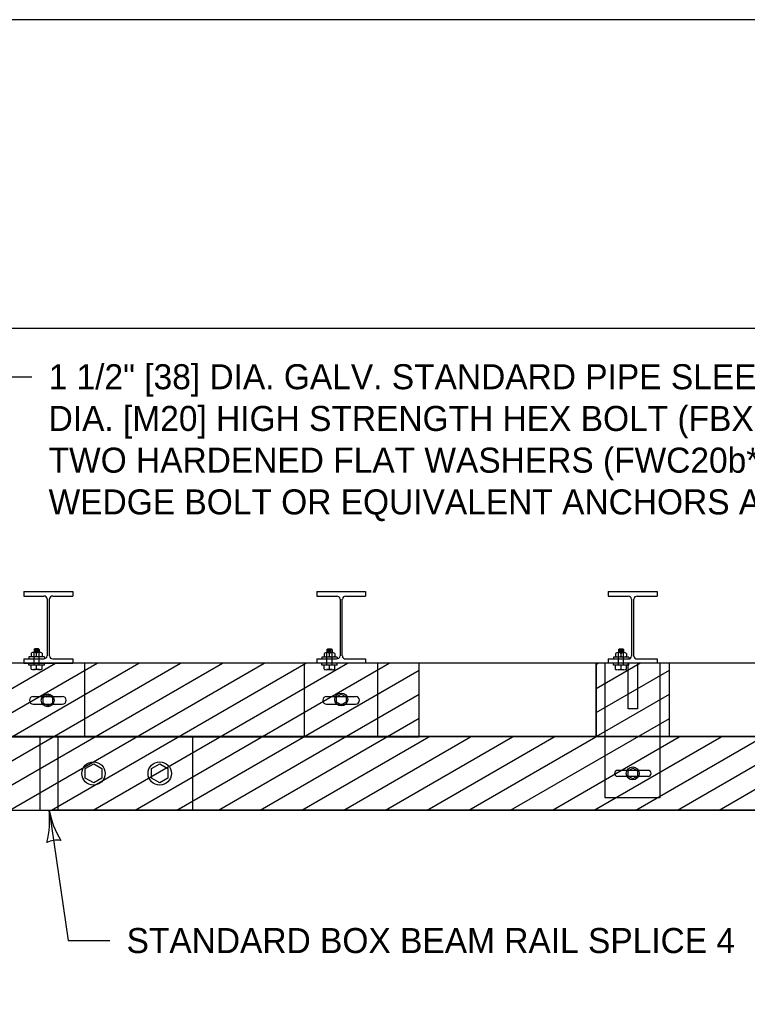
# Model space of a CAD drawing. Extents: x 49983 to 50021, y 49963.5 to 50011.4.
# Drawn here: x 50005.363 to 50007.107, y 49996.667 to 49998.999 of the extents above; entities that cross this region are included whole.
import ezdxf

# ---------------------------------------------------------------- set-up
doc = ezdxf.new("R2010")
doc.units = 0
for name, color, linetype in [('Level 1', 7, 'Continuous'), ('Level 10', 7, 'Continuous'), ('Level 2', 7, 'Continuous'), ('Level 3', 7, 'Continuous'), ('Level 4', 7, 'Continuous')]:
    doc.layers.add(name, color=color, linetype=linetype)

msp = doc.modelspace()

# ---------------------------------------------------------------- linework, layer by layer
at = {"layer": 'Level 1'}
for p, q in [((50005.3733, 49997.628), (50005.4904, 49997.628)), ((50005.3733, 49997.628), (50005.3733, 49997.617)), ((50005.4904, 49997.628), (50005.4904, 49997.617)), ((50006.0751, 49997.6278), (50006.1922, 49997.6278)), ((50006.0751, 49997.6278), (50006.0751, 49997.6168)), ((50006.1922, 49997.6278), (50006.1922, 49997.6168)), ((50006.7737, 49997.6277), (50006.8908, 49997.6277)), ((50006.7737, 49997.6277), (50006.7737, 49997.6167)), ((50006.8908, 49997.6277), (50006.8908, 49997.6167)), ((50005.3733, 49997.617), (50005.421, 49997.617)), ((50005.429, 49997.6102), (50005.429, 49997.4739)), ((50005.4346, 49997.4737), (50005.4346, 49997.6102)), ((50005.4427, 49997.617), (50005.4904, 49997.617)), ((50006.0751, 49997.6168), (50006.1229, 49997.6168)), ((50006.1309, 49997.61), (50006.1309, 49997.4737)), ((50006.1364, 49997.4736), (50006.1364, 49997.61)), ((50006.1446, 49997.6168), (50006.1922, 49997.6168)), ((50006.7737, 49997.6167), (50006.8215, 49997.6167)), ((50006.8295, 49997.6098), (50006.8295, 49997.4735)), ((50006.835, 49997.4733), (50006.835, 49997.6098)), ((50006.8432, 49997.6167), (50006.8908, 49997.6167)), ((50005.3977, 49997.4892), (50005.3989, 49997.4904)), ((50005.3977, 49997.4892), (50005.4099, 49997.4892)), ((50005.3977, 49997.4892), (50005.3977, 49997.482)), ((50005.4087, 49997.4904), (50005.3989, 49997.4904)), ((50005.4081, 49997.4873), (50005.3996, 49997.4873)), ((50005.4081, 49997.4861), (50005.3996, 49997.4861)), ((50005.4081, 49997.4849), (50005.3996, 49997.4849)), ((50005.4099, 49997.4892), (50005.4087, 49997.4904)), ((50005.4099, 49997.4892), (50005.4099, 49997.482)), ((50006.0996, 49997.489), (50006.1008, 49997.4902)), ((50006.0996, 49997.489), (50006.1117, 49997.489)), ((50006.0996, 49997.489), (50006.0996, 49997.4817)), ((50006.1105, 49997.4902), (50006.1008, 49997.4902)), ((50006.11, 49997.4871), (50006.1014, 49997.4871)), ((50006.11, 49997.4859), (50006.1014, 49997.4859)), ((50006.11, 49997.4847), (50006.1014, 49997.4847)), ((50006.1117, 49997.489), (50006.1105, 49997.4902)), ((50006.1117, 49997.489), (50006.1117, 49997.4817)), ((50006.7982, 49997.4888), (50006.7994, 49997.49)), ((50006.7982, 49997.4888), (50006.8103, 49997.4888)), ((50006.7982, 49997.4888), (50006.7982, 49997.4816)), ((50006.8091, 49997.49), (50006.7994, 49997.49)), ((50006.8086, 49997.487), (50006.8, 49997.487)), ((50006.8086, 49997.4857), (50006.8, 49997.4857)), ((50006.8086, 49997.4845), (50006.8, 49997.4845)), ((50006.8103, 49997.4888), (50006.8091, 49997.49)), ((50006.8103, 49997.4888), (50006.8103, 49997.4816)), ((50005.3733, 49997.467), (50005.3733, 49997.456)), ((50005.3733, 49997.467), (50005.421, 49997.467)), ((50005.4225, 49997.4713), (50005.3853, 49997.4713)), ((50005.3853, 49997.4713), (50005.3853, 49997.467)), ((50005.3907, 49997.4799), (50005.3907, 49997.4734)), ((50005.4104, 49997.482), (50005.3972, 49997.482)), ((50005.4081, 49997.4837), (50005.3996, 49997.4837)), ((50005.4038, 49997.4734), (50005.4038, 49997.4799)), ((50005.4169, 49997.4799), (50005.4169, 49997.4734)), ((50005.4225, 49997.4713), (50005.4225, 49997.467)), ((50005.4425, 49997.467), (50005.4904, 49997.467)), ((50005.4904, 49997.467), (50005.4904, 49997.456)), ((50005.4904, 49997.467), (50005.4904, 49997.456)), ((50006.0751, 49997.4667), (50006.0751, 49997.4558)), ((50006.0751, 49997.4667), (50006.1228, 49997.4667)), ((50006.1244, 49997.4711), (50006.0872, 49997.4711)), ((50006.0872, 49997.4711), (50006.0872, 49997.4667)), ((50006.0925, 49997.4797), (50006.0925, 49997.4731)), ((50006.1122, 49997.4817), (50006.0991, 49997.4817)), ((50006.11, 49997.4834), (50006.1014, 49997.4834)), ((50006.1057, 49997.4731), (50006.1057, 49997.4797)), ((50006.1188, 49997.4797), (50006.1188, 49997.4731)), ((50006.1244, 49997.4711), (50006.1244, 49997.4668)), ((50006.1444, 49997.4667), (50006.1922, 49997.4667)), ((50006.1922, 49997.4667), (50006.1922, 49997.4558)), ((50006.1922, 49997.4667), (50006.1922, 49997.4558)), ((50006.7737, 49997.4666), (50006.8214, 49997.4666)), ((50006.7737, 49997.4666), (50006.7737, 49997.456)), ((50006.823, 49997.471), (50006.7858, 49997.471)), ((50006.7858, 49997.471), (50006.7858, 49997.4666)), ((50006.7911, 49997.4796), (50006.7911, 49997.473)), ((50006.8108, 49997.4816), (50006.7977, 49997.4816)), ((50006.8086, 49997.4833), (50006.8, 49997.4833)), ((50006.8042, 49997.473), (50006.8042, 49997.4796)), ((50006.8174, 49997.4796), (50006.8174, 49997.473)), ((50006.823, 49997.471), (50006.823, 49997.4666)), ((50006.843, 49997.4666), (50006.8908, 49997.4666)), ((50006.8908, 49997.4666), (50006.8908, 49997.456)), ((50006.3204, 49997.456), (50003.275, 49997.456)), ((50004.8396, 49997.1042), (50005.4489, 49997.456)), ((50004.9396, 49997.1042), (50005.5489, 49997.456)), ((50005.0396, 49997.1042), (50005.6489, 49997.456)), ((50009.122, 49997.456), (50005.1235, 49997.456)), ((50005.1396, 49997.1042), (50005.7489, 49997.456)), ((50005.2396, 49997.1042), (50005.8489, 49997.456)), ((50005.3396, 49997.1042), (50005.9489, 49997.456)), ((50005.4977, 49997.456), (50005.3659, 49997.456)), ((50005.3733, 49997.456), (50005.4904, 49997.456)), ((50005.4396, 49997.1042), (50006.0489, 49997.456)), ((50005.5396, 49997.1042), (50006.1489, 49997.456)), ((50005.6396, 49997.1042), (50006.2489, 49997.456)), ((50005.7396, 49997.1042), (50006.3204, 49997.4396)), ((50006.3204, 49997.2803), (50006.3204, 49997.456)), ((50006.7444, 49997.2799), (50006.7444, 49997.456)), ((50006.7444, 49997.4534), (50006.7489, 49997.456)), ((50006.7444, 49997.3957), (50006.8489, 49997.456)), ((50006.7444, 49997.338), (50006.9201, 49997.4394)), ((50006.9201, 49997.2799), (50006.9201, 49997.456)), ((50005.4192, 49997.3737), (50005.4305, 49997.3802)), ((50005.4192, 49997.3605), (50005.4192, 49997.3737)), ((50005.4305, 49997.3802), (50005.4417, 49997.3737)), ((50005.4417, 49997.3737), (50005.4417, 49997.3605)), ((50005.8396, 49997.1042), (50006.3204, 49997.3818)), ((50006.1227, 49997.3757), (50006.134, 49997.3822)), ((50006.1227, 49997.3626), (50006.1227, 49997.3757)), ((50006.134, 49997.3822), (50006.1452, 49997.3757)), ((50006.1452, 49997.3757), (50006.1452, 49997.3626)), ((50006.7444, 49997.2802), (50006.9201, 49997.3817)), ((50005.4305, 49997.3544), (50005.4192, 49997.3605)), ((50005.4417, 49997.3605), (50005.4305, 49997.3544)), ((50006.134, 49997.3565), (50006.1227, 49997.3626)), ((50006.1452, 49997.3626), (50006.134, 49997.3565)), ((50005.9396, 49997.1042), (50006.3204, 49997.3241)), ((50006.5396, 49997.1042), (50006.9201, 49997.3239)), ((50003.2457, 49997.2799), (50005.4468, 49997.2799)), ((50006.3204, 49997.2803), (50003.275, 49997.2803)), ((50009.1498, 49997.2803), (50005.1235, 49997.2803)), ((50005.4124, 49997.1041), (50005.4124, 49997.2798)), ((50005.455, 49997.2798), (50005.455, 49997.1041)), ((50006.0396, 49997.1042), (50006.3439, 49997.2799)), ((50006.1396, 49997.1042), (50006.4439, 49997.2799)), ((50006.2396, 49997.1042), (50006.5439, 49997.2799)), ((50013.5013, 49997.2799), (50006.3204, 49997.2799)), ((50006.3396, 49997.1042), (50006.6439, 49997.2799)), ((50006.4396, 49997.1042), (50006.7439, 49997.2799)), ((50006.6396, 49997.1042), (50006.9439, 49997.2799)), ((50006.7396, 49997.1042), (50007.0439, 49997.2799)), ((50006.7664, 49997.2799), (50006.7444, 49997.2799)), ((50006.8982, 49997.2799), (50006.7664, 49997.2799)), ((50006.8396, 49997.1042), (50007.1439, 49997.2799)), ((50006.9201, 49997.2799), (50006.8982, 49997.2799)), ((50006.9396, 49997.1042), (50007.2439, 49997.2799)), ((50007.0396, 49997.1042), (50007.3439, 49997.2799)), ((50005.5205, 49997.2037), (50005.5406, 49997.215)), ((50005.5406, 49997.215), (50005.5598, 49997.2037)), ((50005.6793, 49997.2037), (50005.6994, 49997.215)), ((50005.6994, 49997.215), (50005.7186, 49997.2037)), ((50006.8213, 49997.1985), (50006.8325, 49997.2049)), ((50006.8325, 49997.2049), (50006.8435, 49997.1985)), ((50005.5205, 49997.1803), (50005.5205, 49997.2037)), ((50005.5598, 49997.2037), (50005.5598, 49997.1803)), ((50005.6793, 49997.1803), (50005.6793, 49997.2037)), ((50005.7186, 49997.2037), (50005.7186, 49997.1803)), ((50006.8213, 49997.1857), (50006.8213, 49997.1985)), ((50006.8325, 49997.1793), (50006.8213, 49997.1857)), ((50006.8435, 49997.1857), (50006.8325, 49997.1793)), ((50006.8435, 49997.1985), (50006.8435, 49997.1857)), ((50005.5406, 49997.1691), (50005.5205, 49997.1803)), ((50005.5598, 49997.1803), (50005.5406, 49997.1691)), ((50005.6994, 49997.1691), (50005.6793, 49997.1803)), ((50005.7186, 49997.1803), (50005.6994, 49997.1691)), ((50003.2457, 49997.1042), (50005.4468, 49997.1042)), ((50013.5013, 49997.1042), (50005.4468, 49997.1042))]:
    msp.add_line(p, q, dxfattribs=at)
msp.add_lwpolyline([(49999.3835, 49998.9992), (50016.7501, 49998.9992), (50016.7501, 49987.7988), (49999.3835, 49987.7988)], close=True, dxfattribs=at)
for points in [[(50006.7444, 49997.2799), (50006.3204, 49997.2799), (50006.3204, 49997.456), (50003.275, 49997.456), (50003.275, 49997.2799), (50003.2457, 49997.2799), (50002.2562, 49997.4473), (50002.2558, 49997.4447), (50002.2559, 49997.452), (50001.5623, 49997.4576), (50001.5622, 49997.4503), (50001.7737, 49997.3496), (50002.2274, 49997.2739), (50003.2457, 49997.1042), (50005.4468, 49997.1042), (50005.4633, 49997.1042), (50015.1856, 49997.1042), (50015.1855, 49997.1666), (50015.1344, 49997.1847), (50015.2365, 49997.2209), (50015.1855, 49997.239), (50015.1855, 49997.2799), (50012.5423, 49997.2799)], [(50006.9201, 49997.2799), (50006.9201, 49997.456), (50006.7444, 49997.456), (50006.7444, 49997.2799)], [(50005.4468, 49997.2799), (50006.3204, 49997.2799), (50006.3204, 49997.2803)], [(50007.4472, 49997.2799), (50006.9201, 49997.2799)]]:
    msp.add_lwpolyline(points, dxfattribs=at)
for centre, radius in [((50005.4304, 49997.3673), 0.0155), ((50006.1339, 49997.3693), 0.0155), ((50005.54, 49997.1919), 0.0279), ((50005.6988, 49997.1919), 0.0279), ((50006.8323, 49997.1921), 0.0155)]:
    msp.add_circle(centre, radius, dxfattribs=at)
for centre, radius, start, end in [((50005.4216, 49997.6096), 0.00746, 4.5337, 94.5337), ((50005.4421, 49997.6095), 0.00752, 85.0809, 175.0809), ((50006.1235, 49997.6094), 0.00746, 4.5337, 94.5337), ((50006.1439, 49997.6093), 0.00752, 85.0809, 175.0809), ((50006.822, 49997.6092), 0.00746, 4.5337, 94.5337), ((50006.8425, 49997.6092), 0.00752, 85.0809, 175.0809), ((50005.3972, 49997.4704), 0.0116, 55.616, 124.384), ((50005.3972, 49997.483), 0.0116, 235.616, 304.384), ((50005.4104, 49997.4704), 0.0116, 55.616, 124.384), ((50005.4104, 49997.483), 0.0116, 235.616, 304.384), ((50005.4215, 49997.4745), 0.00753, 265.5645, 355.5646), ((50005.4419, 49997.4743), 0.00736, 184.8165, 274.8165), ((50006.0991, 49997.4701), 0.0116, 55.616, 124.384), ((50006.0991, 49997.4827), 0.0116, 235.616, 304.384), ((50006.1122, 49997.4701), 0.0116, 55.616, 124.384), ((50006.1122, 49997.4827), 0.0116, 235.616, 304.384), ((50006.1234, 49997.4743), 0.00753, 265.5645, 355.5646), ((50006.1438, 49997.4741), 0.00741, 184.3799, 274.3799), ((50006.7977, 49997.47), 0.0116, 55.616, 124.384), ((50006.7977, 49997.4826), 0.0116, 235.616, 304.384), ((50006.8108, 49997.47), 0.0116, 55.616, 124.384), ((50006.8108, 49997.4826), 0.0116, 235.616, 304.384), ((50006.822, 49997.4741), 0.00753, 265.5645, 355.5652), ((50006.8423, 49997.4739), 0.00736, 184.8166, 274.8166)]:
    msp.add_arc(centre, radius, start, end, dxfattribs=at)
at = {"layer": 'Level 10'}
for p, q in [((50005.3977, 49997.4516), (50005.3977, 49997.482)), ((50005.4099, 49997.4516), (50005.4099, 49997.482)), ((50006.0996, 49997.4514), (50006.0996, 49997.4817)), ((50006.1117, 49997.4514), (50006.1117, 49997.4817)), ((50006.7982, 49997.4512), (50006.7982, 49997.4816)), ((50006.8103, 49997.4512), (50006.8103, 49997.4816)), ((50005.3853, 49997.4516), (50005.3853, 49997.456)), ((50005.4225, 49997.4516), (50005.3853, 49997.4516)), ((50005.3907, 49997.4418), (50005.3907, 49997.4516)), ((50005.4104, 49997.441), (50005.3972, 49997.441)), ((50005.4038, 49997.4418), (50005.4038, 49997.4516)), ((50005.4169, 49997.4418), (50005.4169, 49997.4516)), ((50005.4225, 49997.4516), (50005.4225, 49997.456)), ((50005.5197, 49997.2799), (50005.5197, 49997.456)), ((50006.0458, 49997.2803), (50006.0458, 49997.456)), ((50006.0872, 49997.4514), (50006.0872, 49997.4558)), ((50006.1244, 49997.4514), (50006.0872, 49997.4514)), ((50006.0925, 49997.4416), (50006.0925, 49997.4514)), ((50006.1122, 49997.4408), (50006.0991, 49997.4408)), ((50006.1057, 49997.4416), (50006.1057, 49997.4514)), ((50006.1188, 49997.4416), (50006.1188, 49997.4514)), ((50006.1244, 49997.4514), (50006.1244, 49997.4558)), ((50006.2215, 49997.2803), (50006.2215, 49997.4558)), ((50006.7664, 49997.1335), (50006.7664, 49997.456)), ((50006.7858, 49997.4512), (50006.7858, 49997.4556)), ((50006.823, 49997.4512), (50006.7858, 49997.4512)), ((50006.7911, 49997.4414), (50006.7911, 49997.4512)), ((50006.8108, 49997.4406), (50006.7977, 49997.4406)), ((50006.8042, 49997.4414), (50006.8042, 49997.4512)), ((50006.8174, 49997.4414), (50006.8174, 49997.4512)), ((50006.8213, 49997.3466), (50006.8213, 49997.456)), ((50006.823, 49997.4512), (50006.823, 49997.4556)), ((50006.8433, 49997.456), (50006.8433, 49997.3466)), ((50006.8982, 49997.1335), (50006.8982, 49997.456)), ((50005.3959, 49997.3764), (50005.4654, 49997.3764)), ((50006.0987, 49997.3764), (50006.1682, 49997.3764)), ((50006.1682, 49997.3764), (50006.1682, 49997.3764)), ((50005.3959, 49997.3581), (50005.4654, 49997.3581)), ((50006.0987, 49997.3581), (50006.1682, 49997.3581)), ((50006.1682, 49997.3581), (50006.1682, 49997.3581)), ((50006.8433, 49997.3466), (50006.8213, 49997.3466)), ((50006.7885, 49997.1921), (50006.7885, 49997.1921)), ((50006.869, 49997.1994), (50006.7958, 49997.1994)), ((50006.869, 49997.1848), (50006.7958, 49997.1848)), ((50006.8764, 49997.1921), (50006.8764, 49997.1921)), ((50006.8982, 49997.1335), (50006.7664, 49997.1335))]:
    msp.add_line(p, q, dxfattribs=at)
for centre, radius, start, end in [((50005.3972, 49997.4686), 0.0276, 256.2307, 283.7693), ((50005.4104, 49997.4686), 0.0276, 256.2307, 283.7693), ((50006.0991, 49997.4683), 0.0276, 256.2307, 283.7693), ((50006.1122, 49997.4683), 0.0276, 256.2307, 283.7693), ((50006.7977, 49997.4682), 0.0276, 256.2307, 283.7693), ((50006.8108, 49997.4682), 0.0276, 256.2307, 283.7693), ((50005.3959, 49997.3673), 0.00915, 90, 270), ((50005.4654, 49997.3673), 0.00915, 270, 90), ((50006.0987, 49997.3673), 0.00915, 90, 270), ((50006.1682, 49997.3673), 0.00915, 270, 90), ((50006.7958, 49997.1921), 0.00731, 90, 270), ((50006.869, 49997.1921), 0.00731, 270, 90)]:
    msp.add_arc(centre, radius, start, end, dxfattribs=at)
at = {"layer": 'Level 3'}
for p, q in [((50013.5096, 49998.2581), (50005.0789, 49998.2581)), ((50005.2926, 49998.1429), (50005.3926, 49998.1429)), ((50005.4339, 49997.1042), (50005.4794, 49996.7915)), ((50005.4794, 49996.7915), (50005.5794, 49996.7915))]:
    msp.add_line(p, q, dxfattribs=at)
for centre, radius, start, end in [((50005.2128, 49997.0813), 0.2223, 345.7328, 5.9163), ((50005.6626, 49997.1491), 0.233, 191.1041, 210.354), ((50005.4524, 49996.9774), 0.0548, 80.4156, 116.138)]:
    msp.add_arc(centre, radius, start, end, dxfattribs=at)
at = {"layer": 'Level 4'}
msp.add_line((50005.7772, 49997.2799), (50005.7772, 49997.1042), dxfattribs=at)

# ---------------------------------------------------------------- texts
at = {"layer": 'Level 2'}
for s, p in [('1 1/2" [38] DIA. GALV. STANDARD PIPE SLEEVE CAST IN PLACE FOR 3/4" ', (50005.4326, 49998.1129)), ('DIA. [M20] HIGH STRENGTH HEX BOLT (FBX20b*) AND NUT (FNX20b*) WITH', (50005.4326, 49998.0129)), ('TWO HARDENED FLAT WASHERS (FWC20b*) (3/4" x 4" [19 x 102] POWERS', (50005.4326, 49997.9129)), ('WEDGE BOLT OR EQUIVALENT ANCHORS ARE ACCEPTABLE ALTERNATIVE) 2', (50005.4326, 49997.8129)), ('STANDARD BOX BEAM RAIL SPLICE 4', (50005.6194, 49996.7615))]:
    msp.add_text(s, height=0.06, dxfattribs=at).set_placement(p)

doc.saveas('drawing.dxf')
